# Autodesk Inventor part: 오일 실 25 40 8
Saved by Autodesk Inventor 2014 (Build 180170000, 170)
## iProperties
Created: 2025-12
Part Number: 오일 실 25 40 8
Material: 일반
Document SubType Name: Modeling
Designer: dg
Density: 1 g/cm^3
Appearance: 기본값
Author: dg
Author: jhkim
Description: 오일-실
Creation Date: 2025-11-19
Sending System: Autodesk Inventor 2026
Preprocessor: ST-DEVELOPER v20.1
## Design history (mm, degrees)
node "오일 실 25 40 81"
body "Solid1"
node "기준1"
